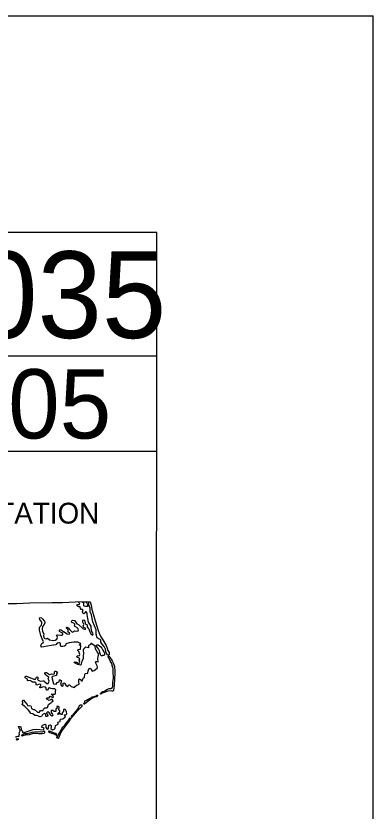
# Model space of a CAD drawing. Extents: x -0.32 to 3.05, y 0 to 1.83.
# Drawn here: x 2.7302 to 2.8333, y 1.6039 to 1.8333 of the extents above; entities that cross this region are included whole.
import ezdxf

# ---------------------------------------------------------------- set-up
doc = ezdxf.new("R2010")
doc.units = 0
for name, color, linetype in [('P_RDY_Limits_of_Construction', 7, 'Continuous'), ('P_RDY_TL_Draft_DNC_Null_Point', 7, 'Continuous'), ('P_RDY_TL_Grass_Shoulder_Normal', 7, 'Continuous')]:
    doc.layers.add(name, color=color, linetype=linetype)

msp = doc.modelspace()

# ---------------------------------------------------------------- linework, layer by layer
at = {"layer": 'P_RDY_TL_Draft_DNC_Null_Point'}
for p in [(0, 1.83333), (2.83333, 0)]:
    msp.add_line(p, (2.83333, 1.83333), dxfattribs=at)
at = {"layer": 'P_RDY_TL_Grass_Shoulder_Normal'}
for p, q in [((2.77083, 1.77083), (0.0625, 1.77083)), ((2.77079, 0.0625), (2.77083, 1.77083)), ((2.77083, 1.73513), (2.60416, 1.73513)), ((2.77083, 1.70763), (2.60416, 1.70763))]:
    msp.add_line(p, q, dxfattribs=at)
for points in [[(2.75162, 1.66423), (2.74731, 1.66411), (2.74363, 1.66397), (2.74121, 1.66399), (2.74052, 1.66391), (2.7342, 1.66382), (2.73038, 1.6637), (2.72744, 1.66369)], [(2.74955, 1.66098), (2.74943, 1.66142), (2.74965, 1.66172), (2.74943, 1.662), (2.74901, 1.66203), (2.74886, 1.66236), (2.74874, 1.6628), (2.74837, 1.66282), (2.74814, 1.66287), (2.74793, 1.66298), (2.7478, 1.66319), (2.74794, 1.66351), (2.74811, 1.66352), (2.74846, 1.66343), (2.74861, 1.66359), (2.74847, 1.66396), (2.74837, 1.66414), (2.74816, 1.66414)], [(2.74928, 1.66417), (2.75046, 1.6642), (2.75077, 1.66367), (2.75086, 1.66327), (2.75083, 1.66287), (2.75028, 1.66293), (2.74989, 1.663), (2.74978, 1.6631), (2.7498, 1.66369), (2.74957, 1.66412), (2.74928, 1.66417)], [(2.75162, 1.66423), (2.75195, 1.66328), (2.75214, 1.66207), (2.75246, 1.66074), (2.75308, 1.65876), (2.75365, 1.65698), (2.75395, 1.65597), (2.75426, 1.65519), (2.75475, 1.65417), (2.75529, 1.65325), (2.75626, 1.65168), (2.7565, 1.65085), (2.75676, 1.65023), (2.7571, 1.64961), (2.75715, 1.64907), (2.75708, 1.64896), (2.75695, 1.64885), (2.7568, 1.64884), (2.75664, 1.64885), (2.75628, 1.64951), (2.75615, 1.64997), (2.75605, 1.65063), (2.75562, 1.6514), (2.7551, 1.65205), (2.75471, 1.65263), (2.7547, 1.65318), (2.75449, 1.65334), (2.75364, 1.65381), (2.75336, 1.65496), (2.75334, 1.65618), (2.7524, 1.65849), (2.75197, 1.6605), (2.75167, 1.6614), (2.75162, 1.66237), (2.75133, 1.66312), (2.75111, 1.66421), (2.75162, 1.66423)], [(2.7382, 1.65889), (2.73847, 1.65872), (2.73851, 1.65821), (2.7383, 1.65771), (2.73786, 1.65713), (2.73776, 1.65646), (2.73787, 1.65568), (2.73821, 1.65501), (2.73813, 1.65446), (2.73827, 1.65397), (2.73856, 1.65366), (2.73896, 1.65359), (2.73933, 1.65377), (2.73989, 1.65332), (2.7409, 1.65309), (2.74151, 1.65321), (2.74196, 1.65349), (2.7422, 1.65391), (2.74205, 1.65423), (2.74192, 1.6546), (2.74222, 1.65473), (2.74313, 1.65459), (2.74352, 1.65467), (2.74371, 1.6548), (2.74372, 1.6551), (2.74342, 1.65527), (2.74276, 1.65569), (2.74276, 1.65606), (2.743, 1.65622), (2.74333, 1.65611), (2.74393, 1.65572), (2.74501, 1.65504), (2.74554, 1.65496), (2.74571, 1.65511), (2.74562, 1.65529), (2.74532, 1.65553), (2.74524, 1.65596), (2.74518, 1.65627), (2.74481, 1.65664), (2.74478, 1.65683), (2.74491, 1.6569), (2.74531, 1.65678), (2.74578, 1.6562), (2.74633, 1.65555), (2.74662, 1.65549), (2.74686, 1.65572), (2.74709, 1.65584), (2.74775, 1.65576), (2.74817, 1.65584), (2.74825, 1.65615), (2.74815, 1.65647), (2.7478, 1.65684), (2.74707, 1.65718), (2.74719, 1.65778), (2.74689, 1.65805), (2.74637, 1.65828), (2.74625, 1.65863), (2.7464, 1.6589), (2.74658, 1.65896), (2.74714, 1.65885), (2.74748, 1.65842), (2.74777, 1.65786), (2.74826, 1.65774), (2.74952, 1.65653), (2.75017, 1.65627), (2.75028, 1.65645), (2.75024, 1.65664), (2.74984, 1.65686), (2.74956, 1.65719), (2.74976, 1.65773), (2.74969, 1.658), (2.74946, 1.65839), (2.74948, 1.65896), (2.7498, 1.65901), (2.75004, 1.65878), (2.75022, 1.65792), (2.75075, 1.65756), (2.75072, 1.65702), (2.75095, 1.65676), (2.75128, 1.65642), (2.75151, 1.65559), (2.75184, 1.655), (2.75236, 1.65467), (2.75237, 1.65474), (2.75249, 1.65497), (2.75237, 1.6552), (2.75211, 1.65566), (2.75204, 1.65614), (2.75193, 1.65674), (2.75195, 1.65719), (2.75171, 1.65754), (2.75113, 1.65841), (2.75095, 1.65939), (2.75073, 1.66062), (2.75073, 1.66101), (2.75048, 1.6614), (2.75025, 1.6614), (2.75005, 1.66111), (2.74984, 1.66076), (2.74955, 1.66098)], [(2.74891, 1.65216), (2.74867, 1.65236), (2.74806, 1.65257), (2.74695, 1.65262), (2.74555, 1.65238), (2.74458, 1.6521), (2.74447, 1.65167), (2.7442, 1.65146), (2.7437, 1.65138), (2.74323, 1.65139), (2.74302, 1.65152), (2.74309, 1.65186), (2.74306, 1.65221), (2.74283, 1.65243), (2.74257, 1.65244), (2.74208, 1.65232), (2.74174, 1.65188), (2.74106, 1.65173), (2.74035, 1.65168), (2.73828, 1.65123), (2.73752, 1.65117), (2.73745, 1.65136), (2.73742, 1.6516), (2.73763, 1.6522), (2.73808, 1.65239), (2.73817, 1.6527), (2.73809, 1.6529), (2.73774, 1.65352), (2.73737, 1.65455), (2.73701, 1.65609), (2.73703, 1.6567), (2.73712, 1.65703), (2.73741, 1.65733), (2.73758, 1.65748), (2.73761, 1.65763), (2.73771, 1.65803), (2.73767, 1.65836), (2.7374, 1.65878), (2.73708, 1.65918), (2.73703, 1.65952), (2.737, 1.65964), (2.73732, 1.65972), (2.73759, 1.65962), (2.73796, 1.65923), (2.7382, 1.65889)], [(2.74189, 1.64299), (2.74073, 1.64272), (2.74057, 1.64252), (2.74065, 1.64198), (2.74105, 1.64056), (2.74181, 1.64051), (2.74213, 1.64098), (2.74269, 1.64115), (2.74279, 1.64174), (2.74301, 1.6417), (2.74335, 1.64143), (2.74308, 1.64052), (2.74338, 1.64001), (2.74358, 1.63986), (2.74387, 1.64001), (2.74384, 1.64073), (2.74401, 1.6409), (2.74426, 1.64074), (2.74472, 1.63999), (2.74515, 1.63984), (2.74533, 1.64031), (2.74568, 1.64029), (2.74617, 1.63985), (2.74711, 1.63954), (2.74742, 1.63994), (2.74785, 1.64026), (2.74826, 1.64035), (2.74843, 1.6405), (2.7484, 1.64119), (2.7484, 1.64187), (2.74858, 1.642), (2.74891, 1.64177), (2.74917, 1.64143), (2.74943, 1.64147), (2.74964, 1.64218), (2.74999, 1.64244), (2.75011, 1.6434), (2.75022, 1.6436), (2.75093, 1.64367), (2.75102, 1.64434), (2.75137, 1.64505), (2.75162, 1.64512), (2.75195, 1.64471), (2.75223, 1.64425), (2.75276, 1.64442), (2.75363, 1.64507), (2.7537, 1.64541), (2.75366, 1.6458), (2.75319, 1.64672), (2.75332, 1.64699), (2.75353, 1.647), (2.75395, 1.64689), (2.75398, 1.64707), (2.7538, 1.64779), (2.75395, 1.64852), (2.75411, 1.64918), (2.75395, 1.64944), (2.75368, 1.64984), (2.75319, 1.65067), (2.75311, 1.65142), (2.75179, 1.65232), (2.75179, 1.65229), (2.75168, 1.65186), (2.75129, 1.65177), (2.75113, 1.65159), (2.75118, 1.65101), (2.75035, 1.65117), (2.75005, 1.65095), (2.74973, 1.65062), (2.74964, 1.65032), (2.74972, 1.64929), (2.74957, 1.64863), (2.74959, 1.64778), (2.74923, 1.64716), (2.74907, 1.64632), (2.74905, 1.64612), (2.74883, 1.64598), (2.7481, 1.64614), (2.74753, 1.64643), (2.7472, 1.64668), (2.747, 1.64692), (2.74765, 1.64682), (2.74847, 1.64648), (2.74868, 1.64683), (2.74848, 1.64749), (2.7486, 1.64783), (2.74831, 1.64805), (2.74785, 1.6482), (2.74781, 1.64846), (2.74799, 1.64864), (2.74855, 1.64876), (2.7486, 1.64902), (2.74839, 1.64989), (2.7481, 1.65017), (2.74809, 1.65036), (2.74829, 1.65053), (2.74884, 1.65061), (2.74896, 1.65155), (2.74843, 1.65184), (2.74891, 1.65216)], [(2.75362, 1.65183), (2.75392, 1.65179), (2.75432, 1.65155), (2.7547, 1.6513), (2.75501, 1.65086), (2.75529, 1.65032), (2.75555, 1.64983), (2.7557, 1.64974), (2.75576, 1.64944), (2.75576, 1.64906), (2.75566, 1.64876), (2.75556, 1.64872), (2.75548, 1.64875), (2.75517, 1.64872), (2.75507, 1.64866), (2.75493, 1.64864), (2.75476, 1.6487), (2.7546, 1.64903), (2.75446, 1.6496), (2.75435, 1.65012), (2.75404, 1.65071), (2.75376, 1.65102), (2.75361, 1.65119), (2.75347, 1.65148), (2.75345, 1.65163), (2.75348, 1.65174), (2.75361, 1.65183)], [(2.75828, 1.64359), (2.75825, 1.64481), (2.75814, 1.64549), (2.758, 1.64581), (2.75802, 1.64625), (2.75739, 1.64723), (2.75703, 1.64805), (2.75684, 1.6483), (2.75683, 1.64842), (2.75684, 1.64851), (2.75692, 1.6486), (2.75703, 1.6486), (2.75724, 1.64845), (2.75743, 1.64807), (2.75773, 1.6477), (2.75793, 1.64717), (2.75832, 1.64649), (2.75862, 1.64554), (2.75879, 1.64423), (2.75875, 1.64342), (2.75868, 1.64204), (2.75855, 1.64022), (2.75841, 1.63876), (2.75822, 1.6385), (2.75802, 1.63846), (2.75782, 1.63857), (2.75673, 1.63842), (2.75645, 1.63841), (2.75492, 1.63777), (2.75481, 1.63767), (2.75461, 1.6376), (2.75452, 1.63766), (2.75466, 1.63776), (2.75477, 1.63792), (2.75497, 1.6382), (2.75527, 1.63837), (2.75554, 1.63834), (2.75579, 1.63844), (2.75614, 1.63873), (2.75661, 1.63906), (2.75708, 1.63923), (2.75757, 1.63928), (2.75806, 1.63949), (2.75813, 1.63995), (2.75819, 1.64108), (2.75833, 1.64211), (2.75837, 1.64276), (2.75828, 1.64357)], [(2.73523, 1.63321), (2.73557, 1.6332), (2.73639, 1.63239), (2.73691, 1.63234), (2.73733, 1.63287), (2.73801, 1.63284), (2.73812, 1.63327), (2.73854, 1.63367), (2.73902, 1.63363), (2.73927, 1.63374), (2.73959, 1.63459), (2.73999, 1.63486), (2.74039, 1.63506), (2.74049, 1.63531), (2.74097, 1.63568), (2.74078, 1.63599), (2.74058, 1.63614), (2.74025, 1.63599), (2.7398, 1.63581), (2.73912, 1.63611), (2.73902, 1.63634), (2.73925, 1.63654), (2.73974, 1.63657), (2.74005, 1.63701), (2.74087, 1.63668), (2.74103, 1.63681), (2.74097, 1.63709), (2.7405, 1.63766), (2.74084, 1.63764), (2.74136, 1.63759), (2.74157, 1.63771), (2.74164, 1.63833), (2.74169, 1.63882), (2.74147, 1.63909), (2.74124, 1.63911), (2.74071, 1.63914), (2.74029, 1.63924), (2.73991, 1.63941), (2.7396, 1.63935), (2.73933, 1.63867), (2.73911, 1.63871), (2.73892, 1.63897), (2.73893, 1.63947), (2.73867, 1.63961), (2.73823, 1.63969), (2.73722, 1.6394), (2.73705, 1.63945), (2.73705, 1.63973), (2.73734, 1.64002), (2.73735, 1.64033), (2.7371, 1.64045), (2.73671, 1.64036), (2.73622, 1.6402), (2.73608, 1.64034), (2.73608, 1.64079), (2.73572, 1.64109), (2.73524, 1.64104), (2.73495, 1.64109), (2.73467, 1.64121), (2.73435, 1.64157), (2.7337, 1.64143), (2.73349, 1.64158), (2.7335, 1.64197), (2.73286, 1.64227), (2.73281, 1.64253), (2.73293, 1.64278), (2.73321, 1.6428), (2.73539, 1.64192), (2.73561, 1.64188), (2.73586, 1.64197), (2.73615, 1.64252), (2.73634, 1.64257), (2.73658, 1.64235), (2.73646, 1.64186), (2.7366, 1.64161), (2.7372, 1.64136), (2.738, 1.6414), (2.73826, 1.64142), (2.73853, 1.64117), (2.73913, 1.64067), (2.7395, 1.64064), (2.73971, 1.64104), (2.73982, 1.64136), (2.73946, 1.64214), (2.73969, 1.64253), (2.73912, 1.64291), (2.73863, 1.64327), (2.73854, 1.64354), (2.73869, 1.64383), (2.73899, 1.64384), (2.7399, 1.64324), (2.74053, 1.64349), (2.7411, 1.64336), (2.74133, 1.64357), (2.74137, 1.644), (2.74141, 1.64424), (2.74167, 1.64424), (2.74217, 1.64394), (2.74188, 1.64342), (2.74189, 1.64299)], [(2.7538, 1.63727), (2.75374, 1.63716), (2.75361, 1.63697), (2.75342, 1.63685), (2.75315, 1.63684), (2.75226, 1.63648), (2.75151, 1.63595), (2.75049, 1.63508), (2.7501, 1.63478), (2.74997, 1.63472), (2.74986, 1.63473), (2.74979, 1.63481), (2.74983, 1.63495), (2.74995, 1.63506), (2.75003, 1.63517), (2.75009, 1.63534), (2.75004, 1.63553), (2.75009, 1.63563), (2.7502, 1.63571), (2.75052, 1.63589), (2.75101, 1.63615), (2.7516, 1.63648), (2.75183, 1.63652), (2.752, 1.63658), (2.75216, 1.63674), (2.75224, 1.6368), (2.75244, 1.63688), (2.75262, 1.63687), (2.75307, 1.63704), (2.75337, 1.63716), (2.75357, 1.6373), (2.75366, 1.63734), (2.75374, 1.63733), (2.75381, 1.63728)], [(2.73753, 1.62808), (2.73789, 1.62865), (2.73865, 1.62893), (2.73883, 1.62879), (2.73878, 1.62794), (2.73921, 1.62754), (2.7395, 1.6276), (2.73956, 1.62782), (2.73971, 1.62869), (2.74006, 1.62872), (2.74036, 1.6286), (2.74032, 1.62817), (2.74023, 1.62767), (2.74073, 1.62733), (2.74127, 1.6275), (2.74153, 1.62779), (2.74165, 1.62851), (2.74237, 1.62892), (2.74241, 1.62914), (2.74227, 1.62949), (2.74294, 1.6297), (2.74296, 1.62993), (2.74307, 1.63043), (2.74371, 1.63049), (2.74419, 1.63085), (2.74448, 1.63102), (2.7443, 1.63128), (2.74424, 1.63159), (2.74463, 1.63168), (2.7449, 1.63188), (2.74483, 1.63248), (2.74463, 1.63297), (2.74433, 1.63323), (2.74392, 1.63315), (2.74389, 1.63252), (2.74358, 1.63219), (2.74353, 1.63172), (2.74341, 1.6317), (2.74319, 1.63176), (2.74305, 1.63197), (2.74276, 1.63191), (2.74236, 1.63172), (2.74227, 1.63185), (2.74239, 1.63214), (2.74282, 1.63247), (2.74291, 1.63279), (2.74256, 1.63313), (2.7427, 1.63363), (2.74265, 1.63398), (2.74227, 1.63414), (2.74198, 1.63406), (2.74205, 1.63359), (2.74175, 1.63337), (2.7417, 1.63295), (2.7417, 1.63261), (2.74124, 1.63263), (2.74088, 1.6329), (2.74041, 1.63287), (2.74033, 1.63232), (2.74072, 1.63173), (2.74083, 1.63141), (2.74064, 1.63129), (2.74026, 1.63147), (2.74006, 1.63187), (2.7397, 1.63239), (2.73927, 1.63243), (2.73905, 1.63222), (2.73913, 1.63191), (2.73938, 1.63143), (2.73929, 1.63111), (2.73879, 1.63111), (2.73882, 1.63151), (2.73874, 1.63193), (2.73853, 1.63202), (2.73808, 1.63185), (2.73778, 1.6315), (2.73755, 1.63111), (2.73719, 1.63102), (2.7369, 1.63118), (2.73656, 1.63138), (2.73613, 1.63141), (2.73569, 1.6314), (2.73508, 1.6319), (2.73446, 1.63206), (2.7342, 1.63249), (2.73381, 1.63299), (2.73268, 1.63413), (2.73192, 1.63459), (2.73205, 1.63479), (2.73214, 1.63507), (2.73208, 1.63558), (2.73215, 1.63586), (2.73238, 1.63586), (2.73276, 1.63539), (2.73347, 1.63465), (2.73361, 1.63428), (2.7341, 1.6343), (2.73447, 1.63421), (2.73473, 1.63349), (2.73523, 1.63321)], [(2.74631, 1.63083), (2.74794, 1.63282), (2.74935, 1.63417), (2.74935, 1.63441), (2.74879, 1.63445), (2.74831, 1.63415), (2.74826, 1.63379), (2.74788, 1.63319), (2.74693, 1.63202), (2.74646, 1.63146), (2.74633, 1.63142), (2.74614, 1.63114), (2.74622, 1.63087), (2.7463, 1.63083)], [(2.74585, 1.63073), (2.74601, 1.63068), (2.74537, 1.62961), (2.74445, 1.62833), (2.74339, 1.62688), (2.74283, 1.62586), (2.74257, 1.62509), (2.74234, 1.62485), (2.74225, 1.62488), (2.74212, 1.62501), (2.74188, 1.62528), (2.74223, 1.62537), (2.74287, 1.62668), (2.74374, 1.62817), (2.74407, 1.62837), (2.74471, 1.6292), (2.74524, 1.62989), (2.74587, 1.63073)], [(2.73012, 1.62512), (2.73039, 1.62535), (2.73078, 1.62544), (2.73108, 1.62549), (2.73108, 1.62572), (2.73119, 1.62604), (2.73113, 1.62646), (2.73141, 1.62699), (2.73144, 1.62717), (2.73119, 1.62758), (2.731, 1.628), (2.73095, 1.62825), (2.73135, 1.62827), (2.73163, 1.6282), (2.73172, 1.6273), (2.73208, 1.62692), (2.73212, 1.62653), (2.7323, 1.62647), (2.73285, 1.62664), (2.73517, 1.6274), (2.73622, 1.6275), (2.7381, 1.62734), (2.73827, 1.62753), (2.73838, 1.62774), (2.73819, 1.62793), (2.73753, 1.62808)], [(2.73057, 1.62438), (2.73103, 1.62466), (2.73057, 1.62467), (2.73049, 1.62471), (2.73042, 1.62472), (2.73035, 1.62466), (2.73029, 1.62455), (2.73032, 1.62446), (2.73039, 1.62441), (2.73046, 1.62437), (2.73057, 1.62438)], [(2.73275, 1.62616), (2.73183, 1.62579), (2.7318, 1.62568), (2.73197, 1.6256), (2.73226, 1.62565), (2.73293, 1.62585), (2.73412, 1.62598), (2.73526, 1.62633), (2.73675, 1.62629), (2.73772, 1.62624), (2.73838, 1.62633), (2.73853, 1.6265), (2.73851, 1.6268), (2.73812, 1.6268), (2.73771, 1.62667), (2.7371, 1.62671), (2.73642, 1.6266), (2.73552, 1.62662), (2.73474, 1.62649), (2.73339, 1.62617), (2.73275, 1.62616)], [(2.73955, 1.62685), (2.73994, 1.62654), (2.74075, 1.62625), (2.74111, 1.62613), (2.74128, 1.62602), (2.74146, 1.62598), (2.74162, 1.62592), (2.74185, 1.62579), (2.74188, 1.62575), (2.74196, 1.62573), (2.74202, 1.62581), (2.74196, 1.62594), (2.7416, 1.62621), (2.74106, 1.62648), (2.74065, 1.6266), (2.74016, 1.62681), (2.73983, 1.62693), (2.73971, 1.62692), (2.73961, 1.62693), (2.73958, 1.62691), (2.73956, 1.62688), (2.73955, 1.62686)]]:
    msp.add_lwpolyline(points, dxfattribs=at)

# ---------------------------------------------------------------- texts
at = {"layer": 'P_RDY_Limits_of_Construction'}
for s, height, p in [('HB-0035', 0.025, (2.64167, 1.74038)), ('005', 0.02, (2.71308, 1.71138))]:
    msp.add_text(s, height=height, dxfattribs=at).set_placement(p)
at = {"layer": 'P_RDY_TL_Grass_Shoulder_Normal'}
msp.add_text('DEPARTMENT OF TRANSPORTATION', height=0.0060037, rotation=0, dxfattribs=at).set_placement((2.60929, 1.68683))

doc.saveas('drawing.dxf')
